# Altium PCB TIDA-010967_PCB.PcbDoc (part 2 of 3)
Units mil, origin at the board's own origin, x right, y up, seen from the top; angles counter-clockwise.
Board outline 2322.7 x 960 mil, 2 copper layers (Top Layer, Bottom Layer), stack 44.731 mil thick; 178 components, 80 nets, 496 pads, 399 vias.
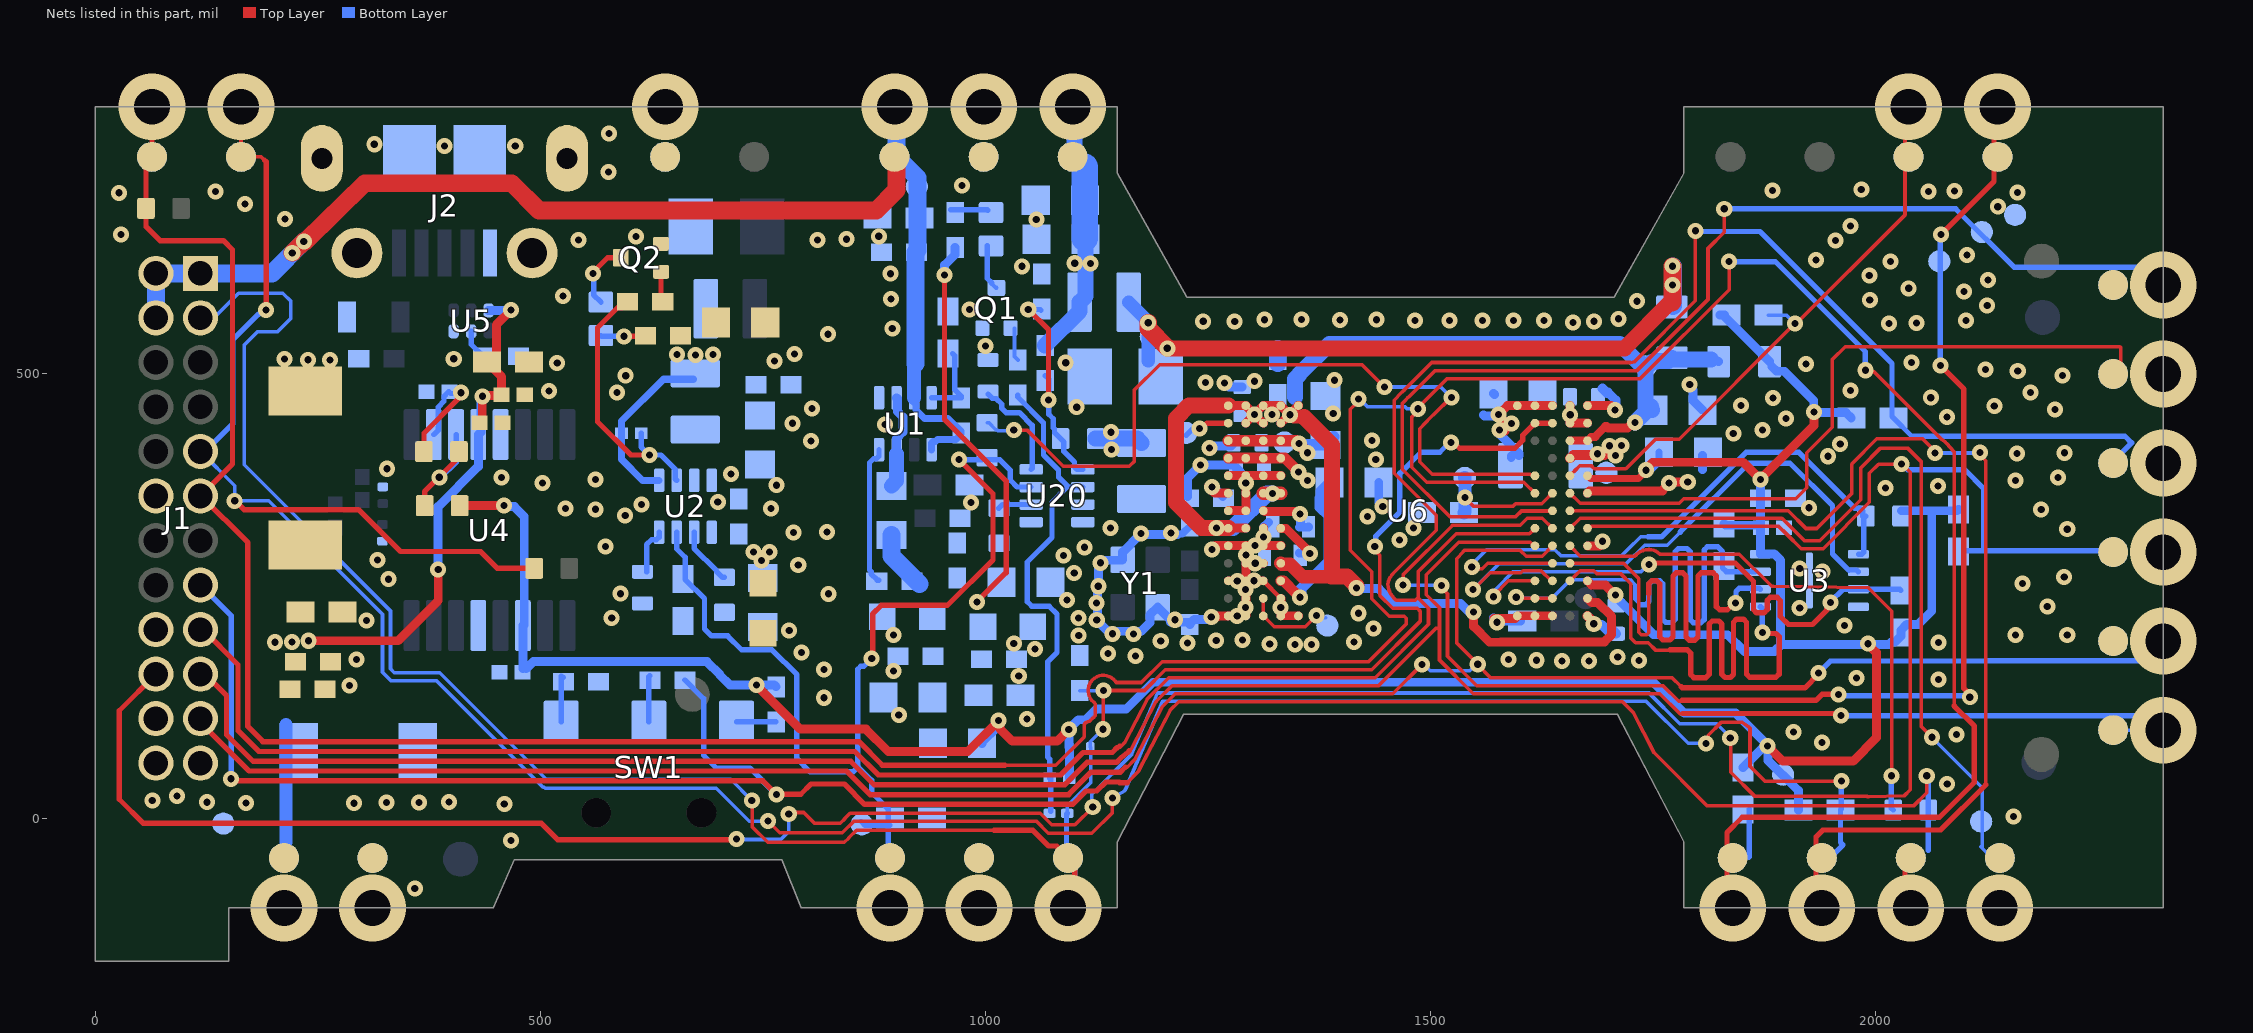
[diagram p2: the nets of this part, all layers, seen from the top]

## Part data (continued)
R14 R15: library part CMP-0027082-3, "RES, 27, 5%, 0.05 W, 0201", Manufacturer="Yageo America", Power_W=50mW, Supplier Part Number 1=YAG2291CT-ND, TempCo="200 ppm/C", Tolerance_%=5%, Value2=0.05W, Value_Code=27R0, ValueDisplayed=27
R19: library part CMP-0026557-2, "RES, 7.87 k, 1%, 0.063 W, AEC-Q200 Grade 0, 0402", Manufacturer=Vishay-Dale, Power_W=63mW, Supplier Part Number 1=541-7.87KLCT-ND, TempCo="100 ppm/C", Tolerance_%=1%, Value2=0.063W, Value_Code=7k87, ValueDisplayed=7.87k
R21: library part CMP-0026574-2, "RES, 82.5 k, 1%, 0.063 W, AEC-Q200 Grade 0, 0402", Manufacturer=Vishay-Dale, Power_W=63mW, Supplier Part Number 1=541-82.5KLCT-ND, TempCo="100 ppm/C", Tolerance_%=1%, Value2=0.063W, Value_Code=82k5, ValueDisplayed=82.5k
R22: library part CMP-0120016-1, "33.2 Ohms ±1% 0.063W, 1/16W Chip Resistor 0402 (1005 Metric) Thin Film", Digikey Part Number=13-RT0402FRE0733R2LCT-ND, Manufacturer=Yageo, Mouser Part Number=603-RT0402FRE0733R2L, Operating Temperature Range="-55°C to +155°C", Power_W=63mW, TempCo=50ppm/°C, Tolerance_%=1%
R23 R175: library part CMP-0027261-3, "RES, 100 k, 1%, 0.05 W, 0201", Manufacturer=Vishay-Dale, Power_W=50mW, Supplier Part Number 1=541-100KAABCT-ND, TempCo="100 ppm/C", Tolerance_%=1%, Value2=0.05W, Value_Code=100k
R26 R244: library part CMP-0026727-1, "RES, 1.00 M, 1%, 0.063 W, 0402", Manufacturer="Yageo America", Power_W=63mW, Supplier Part Number 1=311-1.00MLRCT-ND, TempCo="100 ppm/C", Tolerance_%=1%, Value2=0.063W, Value_Code=1M00, ValueDisplayed=1.00M
R27 R180: library part CMP-0094741-1, "Res Thick Film 0402 18K Ohm 1% 1/16W ±100ppm/°C Molded SMD Paper T/R", Digikey Part Number=541-4757-1-ND, Manufacturer=Vishay, Mouser Part Number=71-CRCW040218K0FKEDC, Operating Temperature Range="-55°C to +155°C", Power_W=63mW, TempCo=100ppm/°C, Tolerance_%=1%
R28 R29 R172 R179: library part CMP-0026704-1, "RES, 510, 1%, 0.1 W, 0402", Manufacturer=Panasonic, Power_W=100mW, Supplier Part Number 1=P510LCT-ND, TempCo="100 ppm/C", Tolerance_%=1%, Value2=0.1W, Value_Code=510R, ValueDisplayed=510
R50: library part CMP-0095013-1, "Res Thick Film 0402 47.5K Ohm 1% 1/16W ±100ppm/°C Molded SMD Paper T/R", Digikey Part Number=13-AC0402FR-0747K5LCT-ND, Manufacturer=Yageo, Mouser Part Number=603-AC0402FR-0747K5L, Operating Temperature Range="-55°C to +155°C", Power_W=62.5mW, TempCo=100ppm/°C, Tolerance_%=1%
R165: library part CMP-0095015-1, "Res Thick Film 0201 10K Ohm 0.5% 0.05W ±50ppm/°C Molded SMD Pressed Carrier T/R", Digikey Part Number=P15980CT-ND, Manufacturer=Panasonic, Mouser Part Number=667-ERJ-1RHD1002C, Operating Temperature Range="-55°C to +125°C", Power_W=50mW, TempCo=50ppm/°C, Tolerance_%=0.5%
R176: library part CMP-0086442-2, "RES SMD 0 OHM JUMPER 1/20W 0201", Manufacturer=Yageo, Power_W=50mW, TempCo=200ppm/°C, Tolerance_%=5%
SW1: library part CMP-0096333-1, "Slide Switch SPDT Surface Mount, Right Angle", Coil Resistance_ohm=80mΩ, Contact Current Rating=100mA, Digikey Part Number=401-2012-1-ND, Manufacturer="C&K Switches", Mouser Part Number=611-AYZ0102AGRLC, Operating Temperature Range="-10°C to +60°C"
TP2 TP4 TP6 TP7 TP8 TP9 TP10 TP11 TP12 TP13 TP14 TP15 TP16 TP17 TP18 TP19: library part CMP-0078143-4, "TEST POINT.  No entry in BOM.", Manufacturer=N/A
U1: library part CMP-0088593-2, "1.6 V to 5 V, 2.5-A Low IQ Power Mux With Manual and Automatic Switchover", Manufacturer="Texas Instruments", Max Supply Voltage=5.5V, Min Supply Voltage=1.6V, Nominal Supply Current=0.5-1uA, Operating Temperature Range=to, Output Voltage=0-5.5V
U2: library part CMP-0092337-2, "2.7-V to 6-V, 2-A Automotive Step-Down Converter in SOT583 Package", Manufacturer="Texas Instruments", Max Supply Voltage=6V, Min Supply Voltage=2.7V, Nominal Supply Current=17uA, Operating Temperature Range="-40°C to +150°C", Output Voltage=0.6-5.5V, Switching Frequency=1.8-4MHz
U3: library part CMP-0078466-1, "ULTRA LOW POWER, 16M-BIT [x 1/x 2/x 4] CMOS MXSMIO (SERIAL MULTI I/O) FLASH MEMORY, SON-8", Manufacturer="Macronix International Co., LTD", Supplier Part Number 1=1092-1178-1-ND
U4: library part CMP-0065473-1, "USB to UART, SSOP-16", Manufacturer=FTDI, Supplier Part Number 1=768-1135-1-ND
U5: library part CMP-0043115-3, "4-Channel ESD Protection Array for High-Speed Data Interfaces, DRY0006A (USON-6)", Breakdown Voltage(Min)(V)=6, IO Capacitance(Typ)(pF)=1.6, IO Leakage Current(nA)=1, Manufacturer="Texas Instruments", Operating Temperature Range="-40 to 85 C", Rating=Catalog
U6: library part CMP-0120794-2, Manufacturer="Texas Instruments", Operating Temperature Range=to
U20: library part CMP-0120069-1, "2.7-V to 6-V, 2-A Step-Down Converter in SOT583 Package", Manufacturer="Texas Instruments", Max Supply Voltage=6V, Min Supply Voltage=2.7V, Nominal Supply Current=17uA, Operating Temperature Range="-40°C to +150°C", Output Voltage=0.6-5.5V, Switching Frequency=1.8-4MHz
Y1: library part CMP-0120019-1, "Crystal Resonator 40MHz ±10ppm (Tol) ±20ppm (Stability) 8pF 50Ohm 4-Pin SMD T/R", Frequency Stability=20ppm, Frequency Tolerance=10ppm, Frequency_Fixed=40MHz, Load Capacitance=8pF, Manufacturer=Murata, Operating Temperature Range="-40°C to +105°C"
ZZ1: library part CMP-0003616-3
ZZ2: library part CMP-0077236-1
ZZ3: library part CMP-0077237-1
ZZ4 ZZ5: library part CMP-0077238-1

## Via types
v1: diameter 18, hole 8, Top Layer to Bottom Layer, tented both sides, 370 vias
v2: diameter 75, hole 40, Top Layer to Bottom Layer, 26 vias
v3: diameter 118.11, hole 118.11, Top Layer to Bottom Layer, tented both sides, 3 vias

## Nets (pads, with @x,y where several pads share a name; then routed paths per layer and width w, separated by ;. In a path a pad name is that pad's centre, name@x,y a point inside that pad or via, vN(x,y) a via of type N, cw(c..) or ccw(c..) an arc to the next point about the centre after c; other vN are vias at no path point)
5V_IN_USB: C25.1 C28.1 C29.2 C30.1 C32.2 C33.1 C36.1 C37.1 C38.1 C45.1 D1.1 J29.1 R5.2 U2.1 U4.12 U5.6 | length 769.7
  Top Layer w10: v1(239.57,200.14) 340.07,200.14 385.22,245.29 v1@385.22,279.99 ; C38.1@431.45,444.93 434.56,448.04 v1@434.56,474.59 ; v1(434.7,474.73) 435.54,475.57 455.58,475.57 C37.1@456.41,476.41 456.41,496.53 C36.1@439.77,513.17 443.71,513.17 450.52,519.98 450.52,555.1 v1(467.07,571.65)
  Bottom Layer w10: v1@384.98,280.22 384.98,350.79 430.24,396.05 U4.12@430.24,431.73 433.18,434.66 433.18,474.29 v1@433.59,474.7 ; U5.6@441.8,571.28 466.7,571.28 v1(467.07,571.65)
  Bottom Layer w15: 214.09,-26.26 214.09,105.87 C33.1@214.09,76.51
  other v1: 201.89,198.46 221.07,198.63 385.13,280.08 748.2,290.16 739.09,300.01 757.16,300.01
  other v2: 212.04,-100
DC_OUT_3V3: C19.1 C49.1 C50.1 L2.2 L3.1 R23.1 R28.1 U2.5 | length 195.3
  Bottom Layer w8: U2.5@633.26,380.3 614.74,380.3 591.06,403.99 591.06,446.91 638.05,493.9 L2.2@671.99,493.9
  other v1: 674.34,521.2 653.5,521.63 693.89,521.63
GND: C1.2 C3.2 C4.2 C5.1 C6.2 C7.2 C8.1 C9.1 C10.2 C11.2 C13.2 C14.1 C15.2 C16.2 C17.1 C18.2 C19.2 C20.1 C21.2 C22.2 C23.2 C25.2 C26.2 C27.1 C28.2 C29.1 C30.2 C31.1 C32.1 C33.2 C34.1 C35.2 C36.2 C37.2 C38.2 C39.2 C40.2 C41.1 C42.1 C43.2 C44.2 C45.2 C46.1 C47.1 C48.1 C49.2 C50.2 C56.2 C60.2 C69.2 C72.2 C73.2 C74.2 C128.2 C129.2 J1.12 J1.18 J1.22 J1.23 J1.24 J2.5 J2.6 J2.7 J2.8 J2.9 J2.10 J2.11 J21.1 J25.1 J28.1 J32.1 Q1.2 Q2.2 R2.1 R10.1 R16.1 R21.1 R25.2 R26.2 R27.2 R180.2 R244.2 TP11.1 TP15.1 U1.1 U2.8 U3.4 U3.9 U4.5 U4.13 U5.3 U6.A1 U6.A3 U6.A4 U6.A5 U6.A6 U6.A7 U6.A9 U6.A10 U6.B7 U6.B9 U6.C8 U6.C9 U6.C10 U6.D8 U6.D9 U6.E1 U6.E7 U6.E8 U6.E9 U6.E10 U6.F8 U6.G9 U6.G10 U6.H1 U6.H9 U6.J7 U6.J8 U6.J9 U6.J10 U6.N1 U6.N3 U6.N4 U6.N5 U20.8 Y1.2 Y1.4 | length 1542.4
  Top Layer w5: U6.C8@1311.9,267.38 U6.B7@1331.58,247.7
  Top Layer w10: v1@1253.42,222.94 1253.42,223.77 1256.59,226.95 1260.08,226.95 1261.12,227.98 U6.A10@1272.39,227.98 ; v1(1254.44,302.6) 1258.76,306.92 U6.E9@1292.21,306.92 ; U6.A10@1272.59,228.18 1292.28,228.18 U6.C9@1292.28,267.55 ; U6.C10@1272.59,267.55 U6.C9@1292.28,267.55 ; U6.G10@1272.59,346.29 1292.28,346.29 1292.28,365.98 1292.22,366.03 v1(1292.22,377.16) ; U6.J10@1272.59,385.66 U6.J9@1292.21,385.66 ; U6.E9@1292.21,306.75 1292.49,307.02 v1(1302.62,307.02) ; U6.E9@1292.21,306.75 U6.D9@1292.28,287.24 ; U6.J9@1292.28,385.66 U6.J7@1331.65,385.66 ; U6.C8@1311.9,267.55 U6.C9@1292.28,267.55 ; U6.D8@1311.96,287.24 U6.D9@1292.28,287.24 ; U6.E8@1311.96,306.92 U6.E7@1331.65,306.92 ; U6.E8@1311.96,307.02 v1(1311.96,316.81) U6.F8@1311.96,326.61 ; U6.B7@1331.65,247.7 1331.65,228.18 U6.A6@1351.33,228.18 ; v1@1571.22,224.97 1594.51,224.97 U6.A5@1595.58,226.03 ; v1@1583.42,435.71 1583.42,446.74 v1(1576.05,454.1) 1586.18,464.23 U6.N5@1597.33,464.23 ; U6.A5@1597.4,228.18 U6.A3@1636.77,228.18 ; U6.N5@1597.4,464.4 U6.N3@1636.77,464.4 ; U6.N1@1676.07,464.23 1702.73,464.23 v1@1707.99,458.97 ; U6.H1@1676.14,365.98 1678.35,368.19 1760.37,368.19 1760.37,369.75 v1(1767.77,377.15) 1768.92,378.31 v1(1788.67,378.31) ; U6.E1@1676.37,306.68 1689.35,306.68 v1@1692.59,309.92 ; U6.C9@1292.28,267.55 U6.D9@1292.28,287.24
  Top Layer w11: U6.A1@1676.07,228.01 1684.35,219.73 v1@1684.35,217.5
  Bottom Layer w8: 1217.08,320.24 1220.83,320.24 C46.1@1229.42,328.84 ; v1(1254.44,302.6) v1@1254.44,304.89
  Bottom Layer w10: v1@1215.37,319.3 1173.99,319.3 1173.76,319.53 1153.95,299.71 Y1.2@1153.95,291.08 1153.39,290.52 1132.53,290.52 1126.67,284.66 1126.67,261.37 1125.69,260.39 1125.69,224.12 v1(1124.83,223.26) 1137.31,210.79 1174.9,210.79 1184.54,220.42 1184.54,229.15 Y1.4@1193.32,237.93 1208.7,222.54 1207.53,221.38 1207.53,220.96 C47.1@1229.56,220.96 ; C6.2@1226.57,362.2 1226.57,382.66 v1(1241.29,397.38) 1278.34,397.38 C9.1@1281.43,394.28 1292.22,383.49 v1(1292.22,377.16) ; C47.1@1229.56,218.22 1229.56,219.26 1234.41,224.1 1251.58,224.1 v1@1252.89,225.41 ; v1@1250.71,417.52 1252.16,418.98 1275.71,418.98 1278.58,421.85 C20.1@1278.58,422.3 ; v1(1268.51,489.86) 1273.43,484.94 C14.1@1288.21,484.94 ; v1(1311.96,316.81) 1311.96,327.52 C22.2@1317.74,333.3 ; C13.2@1328.14,516.13 C13.2@1328.14,516.13 ; 1328.14,532.03 1328.3,532.19 ; C23.2@1441.56,377.89 1441.56,355.42 v1(1446.07,350.91) ; 1559.42,453.79 1560.56,452.65 v1@1575.53,452.65 ; v1@1570.52,225.96 1574.46,222.02 C43.2@1601.03,222.02 ; C26.2@1570.65,477.81 C26.2@1571.65,476.81 ; v1@1574.56,435.02 1599.19,410.39 C27.1@1599.19,408.28 ; C27.1@1590.42,406.19 C27.1@1590.42,407.85 ; 1699.02,479.49 1707.99,470.52 v1@1707.99,458.97 ; v1(1790.89,488.04) 1790.89,485.88 1794.68,482.09 1794.68,469.87 C15.2@1805.42,459.12 ; 1805.01,392.38 1805.19,392.38 C21.2@1805.19,408.39
  Bottom Layer w11: 1692.17,217.84 1699.62,210.38 1705.88,210.38 C17.1@1708.25,208.01 ; C5.1@1692.83,483.52 1697.94,478.41
  Bottom Layer w20: C13.2@1328.06,512.06 1328.06,527.96
  other v1: 358.85,-78.02 466.78,-24.35 2154.77,2.83 459.39,16.83 169.13,18.06 290.6,17.68 125.64,18.79 326.88,18.43 363.52,18.55 397.2,19 63.97,20.57 91.72,25.93 2080.13,39.32 1939.53,86.06 2090.68,94.94 1907.55,97.84 1046.59,112.44 902.46,116.63 818.57,136.12 285.64,149.97 2070.54,156.61 1978.4,158.48 1037.22,160.35 896.6,166.09 818.36,167.83 1618.85,178.25 1647.3,177.54 1677.64,177.44 1733.91,178.07 293.5,179.17 1587.39,178.95 1710.01,181.87 1168.32,183.09 1137.68,185.83 793.1,186.76 1055.55,190.76 1347.39,195.73 1365.88,196.06 1031.67,196.85 1319.14,196.36 1226.59,197.47 2070.4,198.03 1413.91,198.58 1196.72,200.05 1259.04,200.42 1288.53,201.16 1104.59,206 896.73,206.7 2156.91,206.45 2214.94,206.45 1142.37,207.95 1166.11,207.8 779.38,211.79 1435.66,214.06 1964.84,217.41 1683.09,219.18 1574.33,220.86 304.39,222.71 1212.71,223.73 580.01,225.72 1104.28,225.74 1253.47,226.77 1282.6,228.09 1418.88,231.02 1914.45,237.11 1292.14,237.62 1331.48,237.48 2192.51,238.64 1124.76,242.65 1091.44,245.75 590,252.96 823.59,252.88 1292.01,257.91 1126.55,261.37 2164.71,264.48 1282.73,267.07 1301.67,267.56 329.23,269.27 2211.53,271.8 1099.52,276.43 1940.03,277.95 1914.45,281.33 789.56,285.2 1302.85,287.2 1129.05,287.71 316.85,290.78 1087.63,295.96 1292.62,296.65 1110.92,305.14 573.2,305.85 1693.09,311.86 1464.96,313.13 1174.62,320.74 1208.07,321.16 784.26,321.93 821.71,322.19 2214.94,325.44 1140.13,326.59 1480.66,326.69 1428.75,339.53 595.2,340.83 561.65,347.8 2185.68,347.38 528.02,348.74 758.99,348.76 1924.86,349.5 613.44,353.16 983.72,355.31 699.17,356.2 2010.7,371.52 2069.68,374.14 765.02,374.85 502.46,377.34 2156.91,380.06 561.68,381.34 456.05,383.44 2204.7,383.47 713.93,387.29 327.83,393.35 1438.25,403.8 1946.4,407.39 2158.37,410.29 2212.01,411.27 1251.35,416.72 1959.92,421.23 803.67,424.6 1433.88,425.24 1839.81,432.97 1577.32,437.05 1872.83,436.84 887.22,443.12 1590.61,443.99 782.97,444.39 1899.01,449.93 2079.86,451.45 1390.44,455.46 1707.13,459.29 2201.28,460.03 804.99,461.22 1102.36,462.44 1848.44,464.2 2133.01,463.93 1884.43,472.83 2061.66,473.14 586.06,479.02 2173.49,479.05 509.56,480.52 1971.42,481.34 1246.87,490.39 1302.14,491.67 1391.81,492.81 595.76,497.83 2209.57,498.07 2159.35,502.94 2123.26,504.89 1921.41,511.18 518.8,512.24 1090,512.41 2039.95,512.88 762.92,514.26 402.59,516.85 785.29,522.18 999.93,531.35 822.76,544.44 895.18,550.73 2014.87,556.57 2045.59,556.86 1659.96,557.6 1244.41,558.99 1279.82,558.64 1683.57,558.99 1482.21,559.68 1521.1,560.03 1558.24,560.03 1592.96,559.68 1627.33,559.68 2101.12,559.67 1313.15,560.72 1354.81,561.07 1398.2,560.37 1439.17,560.72 1710.99,561.76 981.85,572.09 2125.04,576.59 1731.82,581.55 1993.16,583.07 893.91,583.82 525.15,587.4 2099.12,592.3 2036.85,596.04 2125.77,605.26 1992.58,610.42 893.34,612.43 1041,620.76 2016.43,626.11 1932.84,627.89 2102.25,633.24 810.99,650.1 1954.83,649.87 542.54,650.36 843.66,651.15 607.38,654.1 880.04,654.45 28.82,656.42 1971.46,665.94 213.23,673.95 1056.93,673.46 2136.95,687.66 167.98,690.68 26.45,703.31 2159.14,703.64 134.99,704.9 2059.12,704.84 1883.79,705.69 2088.44,705.4 1983.58,706.81 973.55,711.61 576.26,726.5 392.38,755.74 471.67,756 313.34,757.85 576.79,769.7
  other v2: 311.39,-100 992.59,-100 640.07,800 997.82,800
GPIO_2: J8.1 U6.H2 | length 797.5
  Top Layer w4: U6.H2@1656.45,365.98 1667.74,354.68 1779.23,354.68 1784.1,359.56 1909.89,359.56 1922.43,372.1 1922.43,411.32 1951.16,440.06 1951.16,516.09 1965.64,530.57 2274.14,530.57 2275.15,529.56 2275.15,508.31 J8.1@2266.57,499.73
  other v2: 2322.82,499.73
GPIO_4: R7.1 U6.J4 | length 875.1
  Top Layer w4: v1(1031.65,436.8) 1046.56,436.8 1087.34,396.03 1161.48,396.03 1167.19,401.73 1167.19,482 1195.44,510.25 1422.86,510.25 v1(1447.93,485.18) ; v1(1523.13,473.37) 1522.73,473.37 1503.19,453.82 1502.99,453.82 1491.04,441.88 1491.04,441.68 1487.65,438.29 1487.65,401.17 1501.52,387.3 1611.75,387.3 1612.44,386.61 1615.9,386.61 U6.J4@1617.02,385.49
  Bottom Layer w4: R7.1@1001.68,445.12 1003.85,445.12 1003.85,444.91 1011.49,437.27 1012.75,437.27 1013.83,436.19 1031.04,436.19 v1(1031.65,436.8) ; v1(1447.93,485.18) 1511.31,485.18 v1(1523.13,473.37)
HOST_INTR_GPIO_5: J4.1 R24.2 U6.J2 | length 649.2
  Top Layer w4: U6.J2@1659.69,388.91 1661.58,390.8 ; 1661.54,390.84 1667.31,396.61 1680.39,396.61 1680.59,396.41 1683.77,393.23 1719.27,393.23 1752.49,426.45 1779.01,426.45 1780.29,427.73 1904.49,551.93 1906.23,551.93 2032.7,678.4 v2@2032.7,800
  Bottom Layer w4: R24.2@1879.39,565.99 1899.29,565.99 v1@1907.71,557.57
  other v1: 1908.97,556.46
  other v2: 2036.65,800
NetC2_2: C2.2 R1.1 R2.2 U20.5 | length 252.5
  Top Layer w6: v1(1047.9,572.28) 1070.59,549.59 v1@1070.59,470.57
  Bottom Layer w6: v1(1047.9,572.28) 1061.31,572.28 R2.2@1062.25,571.35 ; C2.2@1066.97,497.78 1070.91,493.84 1070.91,454.64 1076.02,449.52 1076.02,439.45 1077.35,438.13 1077.35,433.97 1087.94,423.38 1087.94,412.82 1099.84,400.92 1099.84,395.42 1102.75,392.51 U20.5@1109.3,392.51
  other v1: 1070.68,470.45
NetC40_1: C40.1 R13.1 U4.10 | length 149.5
  Top Layer w6: R13.1@369.12,412.51 369.12,433.26 405.92,470.05 408.46,472.59 408.46,476.56 v1@409.78,477.88
  Bottom Layer w6: U4.10@380.24,431.73 385.27,436.75 385.27,462.77 391.73,469.23 391.73,474.62 C40.1@397,479.89 ; C40.1@398.77,478.52 399.4,477.88 v1@409.78,477.88 ; v1@409.78,477.79 v1@410.66,477.79
  other v1: 410.75,478.74
NetD1_2: D1.2 L1.2
  other v1: 238.73,515.72 263.58,515.43 212.68,516.46
NetD2_1: D2.1 Q2.3 | length 72.4
  Top Layer w6: v1(559.08,612.56) 559.08,614.06 575.34,630.31 Q2.3@590.14,630.31
  Bottom Layer w6: v1@559.68,610.18 559.68,588.69 D2.1@567.93,580.44
NetD2_2: D2.2 R28.2 | length 50.7
  Top Layer w6: v1(593.73,542.11) 617.05,542.11 R28.2@617.86,542.92
  Bottom Layer w6: D2.2@567.93,543.04 568.87,542.11 v1(593.73,542.11)
NetD3_1: D3.1 Q1.3 | length 52.2
  Bottom Layer w4.8: 1001.86,607 1001.97,607.1 ; Q1.3@1006.65,601.46 1011.61,596.5 Q1.3@1012.23,596.5
  Bottom Layer w6: 1001.86,607 Q1.3@1007.03,601.83 ; 1001.97,607.1 D3.1@1001.97,644.19
NetD3_2: D3.2 R172.2 | length 41.8
  Bottom Layer w6: R172.2@961.03,684.13 1001.99,684.13 D3.2@1002.59,683.53
NetL4_1: L4.1 U1.2 U1.7 | length 102.6
  Bottom Layer w10: U1.7@899.98,414.75 899.98,427.59 907.22,434.84 907.22,451.4 900.88,457.74 900.88,472.11 U1.2@899.98,473.02
  Bottom Layer w17: L4.1@894.26,374.11 899.94,379.8 U1.7@899.94,410.06
NetQ1_1: Q1.1 R179.1 | length 36.6
  Bottom Layer w4.5: Q1.1@1032.53,550.72 1032.53,519.2 R179.1@1036.12,515.61
NetQ2_1: Q2.1 R29.1 | length 33.5
  Top Layer w6: Q2.1@635.42,614.57 635.42,585.39 R29.1@638.48,582.33
NetR3_1: R3.1 U20.2 | length 37.8
  Bottom Layer w6: R3.1@1014.95,349.1 1019,353.14 U20.2@1051.03,353.14
NetR5_1: R5.1 U2.2 | length 65.9
  Bottom Layer w6: U2.2@672.63,322.04 672.63,303.94 697.69,278.89 697.69,278.16 704.53,271.32 R5.1@706.5,271.32
NetR12_2: R12.2 R13.2 U4.11 | length 128.1
  Top Layer w6: R12.2@369.94,351.84 369.94,367.78 406.72,404.56 R13.2@406.72,407.64
  Bottom Layer w6: v1(386.36,383.78) 388.5,383.78 405.24,400.52 U4.11@405.24,431.73
NetR16_2: R16.2 U5.2 | length 33.8
  Bottom Layer w6: U5.2@422.12,547.65 422.12,533.19 R16.2@435.78,519.53
NetR20_2: R20.2 SW1.2 | length 52.2
  Bottom Layer w6: SW1.2@621.72,109.24 621.72,159.85 R20.2@622.86,160.99
NetR22_2: R22.2 U6.E2 | length 620.7
  Top Layer w4: U6.E2@1656.39,306.75 1667.95,295.18 1681.73,295.18 1729.01,295.18 1730.84,297.01 ; 1730.03,295.96 cw(c1744.98,282.56) 1745.13,302.64 cw(c1745,285.64) 1757.22,297.45 1846.44,297.45 1880.22,264.21 1883.03,261.45 1884.63,261.43 1991.44,259.88 1992.59,258.73 2017.89,233.43 v1@2017.89,48.62
  Bottom Layer w6: v1@2017.4,48.13 2017.4,12.04 R22.2@2019.49,9.95
  other v1: 2017.75,48.48
NetR27_1: R27.1 U2.4 | length 53.8
  Bottom Layer w6: R27.1@619.5,277.35 619.32,277.52 619.32,308.1 624.86,313.63 630.36,313.63 633.26,316.54 U2.4@633.26,322.04
NetR180_1: R180.1 U20.4 | length 116.9
  Bottom Layer w6: R180.1@1002.72,477.08 1007.6,472.2 1011.84,472.2 1018.28,465.77 1018.28,461.12 1022.96,456.43 1027.62,456.43 1027.74,456.31 1038.12,456.31 1052.33,442.1 1052.33,393.81 U20.4@1051.03,392.51
NetTP10_1: TP10.1 U6.M10 | length 52.6
  Top Layer w6: v1@1239.31,438.03 1242.31,438.03 1248.83,444.55 U6.M10@1272.53,444.55
  Bottom Layer w6: TP10.1@1225.54,431.1 1232.47,438.03 v1@1239.31,438.03
  other v1: 1240.22,438.53
OUT_3V3: C1.1 C3.1 J1.1 J1.2 J1.4 J22.1 R9.2 TP6.1 U1.3 U1.5 | length 1456
  Top Layer w20: v1@221.31,635.88 v1(234.13,648.47) v1@235.08,648.47 ; v1@235.79,648.46 302.56,714.06 467.7,714.06 498.31,683.45 877.11,683.45 900,706.33 J22.1@900,743.75
  Bottom Layer w8: U1.3@920.35,467.32 921.83,465.84 921.83,459.22 931.23,449.83 957.46,449.83 965.83,441.46 966.61,441.46 972.45,435.61 972.45,432.09 966.61,426.24 945.94,426.24 943.63,423.94 941.25,423.94 939.35,422.03 U1.5@939.35,414.75
  Bottom Layer w10: 919.66,509.66 920.71,510.7
  Bottom Layer w15: 920.71,510.7 921.27,511.27 ; C1.1@922.31,636.34 C1.1@924.64,638.67
  Bottom Layer w16: U1.3@919.66,473.02 919.66,509.66
  Bottom Layer w20: J1.4@68.1,562.73 J1.2@68.1,612.73 198.38,612.73 v1(234.13,648.47) ; v2@900,800 900,743.75 923.6,720.15 923.6,675.03 C1.1@923.6,638.75 ; 921.27,511.27 C1.1@921.27,636.42
  other v1: 221.2,635.77
  other v2: 897.82,800
PMIC_CLKOUT_SOP1: R25.1 TP8.1 U6.H3 | length 146.6
  Top Layer w4: v1@1538.8,360.26 1548.01,351.05 1592.37,351.05 1595.27,353.95 ; 1595.5,353.96 1624.66,353.96 1629.15,358.44 ; 1629.16,358.43 U6.H3@1636.27,365.53
  Bottom Layer w15: R25.1@1537.38,344 1538.45,345.07 v1(1538.45,360.86) 1538.45,382.76 TP8.1@1538.18,383.04
QSPI_CS: R50.2 U3.1 U6.D3 | length 678.6
  Top Layer w4: v1@1545.3,281.26 1557.87,281.26 ; 1557.87,280.97 1563.96,287.07 U6.D3@1636.7,287.07 ; U6.D3@1636.65,287.12 U6.D3@1636.77,287.24
  Bottom Layer w4: v1@1541.51,281.26 1562.68,302.43 1639.44,302.43 1646.02,295.85 1714.55,295.85 1721.33,302.64 1735.73,317.03 1744.09,317.03
  Bottom Layer w6: 1744.22,316.9 1759.17,316.9 1854.05,411.78 1913.51,411.78 1976.45,348.85 1981.95,348.85 1985.13,345.66 R50.2@1985.13,340.16 ; U3.1@1980.4,297.32 1984.28,297.32 1986.2,299.24 1986.2,337.58 R50.2@1988.79,340.16
  other v1: 1546.08,282.92
QSPI_D0: U3.5 U6.C2 | length 675.1
  Top Layer w4: U6.C2@1656.39,267.38 1663.2,274.19 1667.9,278.88 1678.91,278.88 1683.12,278.91 1686.85,275.19 1695.44,275.19 1703.89,275.19 1713.68,275.19 1724.65,264.21 1724.65,203.24 1730.06,197.83 1744.35,197.83 1752.47,189.71 1768.57,189.71
  Top Layer w6: 1768.74,189.88 1788.46,189.88 1791.98,186.37 1791.98,162.23 1795.49,158.72 1809.18,158.72 1812.69,162.23 1812.69,218.8 1816.21,222.31 1823.54,222.31 1827.06,218.8 1827.06,162.44 1830.57,158.92 1836.54,158.92 1840.05,162.44 1840.05,220.95 1843.57,224.47 1851.13,224.47 1854.65,220.95 1854.65,162.64 1858.16,159.13 1887.84,159.13 1891.36,162.64 1891.36,204.82 1887.84,208.34 1873.57,208.34 v1(1872.43,209.48)
  Bottom Layer w6: U3.5@1870.16,238.26 1870.51,238.26 1872.43,236.34 v1(1872.43,209.48)
QSPI_D1: U3.2 U6.C3 | length 675.3
  Top Layer w4: v1@1547.1,256.85 1566.69,276.44 1601.24,276.44 1603.69,278.89 1621.96,278.92 ; 1623.91,278.95 1635.48,267.38 U6.C3@1636.7,267.38
  Bottom Layer w4: v1@1547.76,257.8 1576.82,286.85 1719.67,286.85 1740.23,307.41 1765.49,307.41 1780.16,322.08
  Bottom Layer w6: 1780.16,322.08 1857.6,399.52 1903.62,399.52 1951.31,351.83 1951.31,297.59 U3.2@1969.89,279.01 ; U3.2@1969.89,279.55 1978.26,279.55 U3.2@1980.29,277.52
  other v1: 1547.61,257.8
QSPI_D2: R44.1 U3.3 U6.C4 | length 629.4
  Top Layer w4: v1(1570.39,249.63) v1@1571.65,250.88 ; v1@1571.15,251.38 1587.15,267.38 U6.C4@1617.02,267.38
  Top Layer w6: v1(1745,285.64) 1746.82,287.45 1842.03,287.45 1862.47,267.01 1862.47,234.97 1865.98,231.45 1874.32,231.45 1877.84,234.97 1877.84,245.32 1881.35,248.83 1889.07,248.83 1892.59,245.32 1892.59,227.5 1901.72,218.37 1928.8,218.37 1944.71,234.28 1944.71,235.57 1949.17,240.03 v1(1949.17,243.28)
  Bottom Layer w4: v1(1570.39,249.63) 1573.07,252.31 1573.07,258.16 1592.76,277.85 1736.52,277.85 1744.3,285.64 v1(1745,285.64)
  Bottom Layer w6: v1(1949.17,243.28) 1949.17,244.16 1962.95,257.95 2026.66,257.95 R44.1@2028.01,256.59
QSPI_D3: R49.1 U3.7 U6.B3 U6.B4 | length 668.4
  Top Layer w4: v1@1594.81,248.08 1595.02,247.87 U6.B3@1636.77,247.87
  Bottom Layer w4: v1@1595.02,247.87 1636.14,247.87 1652.49,264.21 1657.13,268.85 1723.72,268.85 1728.36,264.21 1729.2,263.38 ; 1729.39,263.18 1729.39,246.73 1735.43,240.69
  Bottom Layer w6: v1@1594.81,248.08 v1@1595.02,247.87 ; 1735.43,240.69 1741.51,240.69 1745.02,244.2 1745.02,264.12 1748.54,267.64 1757.05,267.64 1760.56,264.12 1760.56,224.11 1764.08,220.6 1771.14,220.6 1774.65,224.11 1774.65,252.98 1774.65,300.32 1778.17,303.84 1787.89,303.84 1791.4,300.32 1791.4,252.98 1791.4,223.88 1794.92,220.36 1803.58,220.36 1807.09,223.88 1807.09,302.07 1810.61,305.58 1822.47,305.58 1827.72,300.33 1827.72,282.09 1832.1,277.7 U3.7@1863.84,277.7
  other v1: 1596,249.05
QSPI_SCLK: U3.6 U6.D2 | length 671.3
  Top Layer w4: U6.D2@1656.39,286.97 1716.72,286.97 1725.81,277.88 ; 1725.83,277.89 1733.69,270.02 1733.69,209.73 1736.4,207.02 ; 1736.4,206.83 1742.42,206.83 1744.76,209.18 1744.76,252.98
  Top Layer w6: 1744.76,252.98 1744.76,264.12 1748.28,267.64 1753.68,267.64 1757.2,264.12 1757.2,252.98 1757.2,204.49 1760.71,200.97 1768.68,200.97 1772.19,204.49 1772.19,272.94 1775.71,276.45 1783.16,276.45 1786.67,272.94 1786.67,204.4 1790.19,200.88 1796.62,200.88 1800.13,204.4 1800.13,272.94 1803.65,276.45 1817.24,276.45 1820.75,272.94 1820.75,252.98 1820.75,238.47 1824.27,234.96 1833.39,234.96 1840.9,242.47 v1(1842.15,242.47)
  Bottom Layer w6: v1(1842.15,242.47) 1842.96,243.27 1842.96,252.98 1842.96,255.43 1846.47,258.95 1869.16,258.95 U3.6@1870.16,257.95
RADAR_1P2_RF: C20.2 C44.1 TP14.1 U6.L7 U6.L8 U6.L9 U6.L10 | length 136.6
  Top Layer w13: U6.L10@1272.59,425.03 v1@1349.01,425.03 ; v1@1352.18,422.84 1352.18,420.73 v1(1361.62,411.29)
  Bottom Layer w13: v1@1351.69,423.41 1355,420.11 C44.1@1381.93,420.11 C44.1@1391.18,429.35
  other v1: 1352.01,421.92
RADAR_1V2: C27.2 TP13.1 U6.K2 | length 61.4
  Top Layer w10: v1@1695.03,410.68 v1@1699.21,414.3 ; v1@1711.76,417.82 v1@1713.36,417.71
  Top Layer w11: U6.K2@1656.39,405.18 1660.14,408.93 v1@1695.03,408.93
  Top Layer w12: v1@1699.21,414.3 1703.92,418.38 v1@1711.76,417.82
  other v1: 1707.5,408.26 1687.42,410.15 1700.69,419.14 1714.1,419.42
RADAR_1V4_APLL: C22.1 U6.G8 | length 68.7
  Top Layer w10: U6.G8@1311.96,346.29 1312.95,346.29 1313.82,345.41 1354.37,345.41 v1@1355.66,344.12
  Bottom Layer w10: 1352.73,327.66 1353.68,327.66 ; v1@1352.9,341.26 1353.68,340.48 1353.68,327.66 ; C22.1@1362.73,328.1 1362.29,327.66 1353.68,327.66
  other v1: 1353.34,342.7
RADAR_1V4_SYNTH: C18.1 U6.F7 | length 57.1
  Top Layer w10: U6.F7@1331.58,326.44 1337.33,326.44 1364.15,299.62 v1(1364.15,298.19)
  Bottom Layer w10: C18.1@1352.66,298.99 1352.75,298.9 v1@1364.57,298.9
RADAR_1V8: C13.1 C14.2 C15.1 R6.2 R11.1 TP12.1 U6.B1 U6.D7 U6.F9 U6.F10 U6.H7 U6.H8 U6.L1 U6.L2 U6.M7 U6.M8 U6.M9 U6.N6 U6.N7 U6.N8 U6.N9 U6.N10 | length 1823.5
  Top Layer w9: U6.L2@1656.39,424.86 U6.L1@1676.07,424.86 1679.96,428.75 1685.07,428.75 ; 1684.45,429.38 1695.97,440.9
  Top Layer w10: U6.F10@1272.59,326.61 U6.F9@1292.28,326.61 ; U6.N10@1272.59,464.4 1292.28,464.4 1292.28,463.87 v1@1301.99,454.42 ; U6.M9@1292.28,444.72 v1@1301.99,454.42 ; U6.M8@1311.96,444.72 1302.16,454.25 v1@1301.99,454.42 ; U6.M7@1331.65,444.72 1331.77,444.72 v1@1337.22,450.16 ; v1@1341.11,454.55 1331.65,464.01 1331.65,464.4 1311.96,464.4 v1@1301.99,454.42 ; v1@1341.3,454.72 1350.98,464.4 U6.N6@1351.33,464.4 ; v1@1343.15,451.76 1345.69,449.23 1357.72,449.23 ; v1@1548.17,232.25 1548.17,216.24 1565.96,198.45 1578.6,198.45 1579.1,198.95 1695.06,198.95 1703.09,206.98 1703.09,227.46 1687.62,242.93 1680.8,242.93 U6.B1@1676.07,247.7 ; 1695.97,440.9 1697.23,440.9 1699.02,439.11 1720.95,439.11 1727.12,445.28 v1(1729.28,445.28)
  Top Layer w15: U6.H8@1311.96,365.98 U6.H7@1331.65,365.98 ; U6.D7@1331.58,287.07 1332.6,286.05 1342.25,286.05 1356.09,272.21 1388.59,272.21
  Top Layer w18: U6.F10@1272.59,326.61 1242.56,326.61 1213.92,355.24 1213.92,449.95 1228.38,464.4 U6.N10@1272.59,464.4 ; 1357.72,451.2 1388.86,420.06 1388.86,272.21 ; 1388.59,272.21 1388.86,272.21 ; v1(1416.58,259.3) 1416.58,261.66 1406.03,272.21 1388.86,272.21
  Bottom Layer w10: v1@1417.24,258.64 1441.71,258.64 1458.42,241.93 1533.46,241.93 v1@1542.91,232.48 ; R11.1@1823.19,514.01 R11.1@1823.52,513.68
  Bottom Layer w18: v1(1259.21,326.98) 1277.77,326.98 1316.2,365.41 v1(1322.11,365.41) ; 1347.51,473.91 1347.51,494.04 1351.98,498.52 1351.98,499.22 1386.3,533.53 1712.3,533.53 1733.92,511.92 1736.38,511.92 1738.54,509.76 TP12.1@1738.54,508.64 ; v1(1729.28,445.28) 1747.46,463.45 C15.1@1747.62,463.45 ; C15.1@1741.4,463.45 TP12.1@1741.4,504.43 ; TP12.1@1743.67,508.42 1748.77,513.51 1751.7,513.51 1752.32,514.14 1767.17,514.14 R6.2@1770.96,517.93 ; C15.1@1747.62,459.12 C15.1@1748.31,459.12 ; R6.2@1770.96,515.84 R11.1@1814.59,515.84
  other v1: 1547.98,232.45 1302.03,454.12 1321.88,454.12 1341.83,453.98
RADAR_1V_RF_OUT: C9.2 C23.1 U6.C7 U6.K7 U6.K8 U6.K9 U6.K10 | length 278.3
  Top Layer w12: U6.K10@1272.59,405.35 U6.K8@1311.96,405.35 ; U6.K8@1311.9,405.18 U6.K7@1331.58,405.18 ; U6.K7@1331.58,405.35 1336.01,405.35 v1@1351.08,390.28 ; U6.C7@1331.87,267.55 1334.59,267.55 1348.48,253.66 1348.59,253.66 1351.59,250.66 v1@1353.22,250.66 ; v1(1351.32,389.53) 1352.25,389.53 v1(1361.77,380.01)
  Bottom Layer w12: v1(1353.2,248.94) 1354.35,250.09 1354.35,258.52 1385.44,289.61 1385.44,340.45 1375.7,350.18 1375.7,360.12 1376.7,361.12 1376.7,368.14 C23.1@1386.45,377.89
RADAR_3V3: C17.2 C21.1 C34.2 C35.1 C39.1 L7.2 R4.1 R11.2 R12.1 R19.2 R24.1 R44.2 R49.2 R50.1 R73.1 R74.1 R75.1 R165.2 R175.1 TP9.1 U3.8 U4.3 U6.C1 U6.J1 | length 3633.9
  Top Layer w8: U6.J1@1676.07,385.49 1676.57,385.49 1679.58,382.48 1733.49,382.48 v1@1739.6,388.59
  Top Layer w10: R12.1@409.31,351.84 R12.1@409.31,351.84 459.07,351.89 v1(459.13,351.94) ; v1(742.46,150.29) 791.94,100.81 865.55,100.81 890.6,75.76 979.93,75.76 v1(1014.57,110.4) 1016.1,108.86 1016.1,101.48 1030.12,87.47 1080.29,87.47 v1(1093.45,100.63) ; U6.C1@1676.07,267.38 1680.76,262.7 1696.14,262.7 v1@1707.41,251.43 ; v1@1741.01,392.46 1749.18,400.62 1850.98,400.62 v1@1870.67,380.93 ; v1@1870.55,382.01 1930.67,442.13 v1(1930.67,457.21) ; v1(1878.25,82.07) 1895.4,64.92 1974.36,64.92 2000.62,91.18 2000.62,186.8 v1@1991.2,196.23
  Bottom Layer w8: v1(1741.76,391.71) 1746.49,391.71 1757.15,402.37 1756.28,403.24 C21.1@1756.28,411.93
  Bottom Layer w10: v1(459.13,351.94) 460.21,350.86 470.63,350.86 481.84,339.65 U4.3@481.84,218.03 ; C39.1@480.24,168.78 U4.3@480.24,217.16 ; C39.1@484.01,168.78 491.96,176.73 687.02,176.73 701.96,161.78 ; 701.67,161.49 712.6,150.56 762.52,150.56 R19.2@764.63,148.44 ; L7.2@995.83,84.96 995.83,85.94 v1@1013.04,103.16 ; R175.1@1094.16,45.81 1094.16,80.16 R165.2@1093.95,80.38 1093.45,80.87 v1(1093.45,100.63) 1104.21,111.39 1112.43,111.39 1124.51,123.46 1158.01,123.46 1188.02,153.48 1750.16,153.48 1784.78,118.87 1842.46,118.87 v1@1878.76,82.58 ; C17.2@1713.06,244.31 1750.43,206.94 1833.3,206.94 1852.1,188.14 1885.92,188.14 1894.79,197 ; R24.1@1825.07,565.99 R24.1@1830.06,565.99 ; R49.2@1829.52,331.59 1831.26,329.84 C34.2@1867.84,329.84 ; R24.1@1831.25,563.03 R11.2@1880.61,513.68 ; R73.1@1850.85,57.9 v1@1875.02,82.07 ; U3.8@1870.16,297.32 U3.8@1870.4,297.56 ; C35.1@1870.4,357.2 U3.8@1870.4,297.56 ; C35.1@1870.43,359.96 v1@1870.43,383.8 ; v1@1878.9,82.07 1878.9,65.48 1879.19,65.48 TP9.1@1896.17,48.49 ; R11.2@1883.07,508.21 1888.4,502.88 1897.25,502.88 1930.24,469.9 v1@1930.24,457.21 ; 1893.03,197 1893.03,290.48 1885.74,297.77 1870.62,297.77 U3.8@1870.4,297.56 ; 1893.61,195.82 2014.49,195.82 2017.26,198.6 2021.2,198.6 2028.01,205.41 2028.01,211.63 2034.82,218.44 2047.69,218.44 2062.8,233.56 2062.8,346.12 ; TP9.1@1896.31,48.63 1913.03,31.91 R74.1@1913.03,10.2 ; v1@1930.24,456.56 1966.31,456.56 R4.1@1972.36,450.51 ; R50.1@2028.62,346.12 2062.8,346.12 ; R75.1@2092.97,347.8 2091.29,346.12 2062.8,346.12
  other v1: 1991.05,196.83 1707.65,251.49 1870.55,381.2
RADAR_NRST: C48.2 J1.3 J3.1 R165.1 R176.1 U6.M3 U6.M4 | length 2673.6
  Top Layer w4: v1@743.57,22.4 737.66,16.49 737.66,-8.64 755.3,-26.28 841.33,-26.28 846.09,-21.52 846.09,-21.27 851.36,-16 851.61,-16 855.02,-12.59 1009.82,-12.59 ; v1(1131.7,100.75) 1132.21,101.26 v1(1132.21,144.28) 1178.49,144.28 1201.96,167.74 1433.9,167.74 1488.01,221.85 1488.01,233.53 1484.94,236.59 1457.24,236.59 1443.07,250.76 ; v1(1437.17,305.95) 1437.17,302.16 1441.65,297.68 1441.65,297.21 1442.89,295.97 1442.89,251.95
  Top Layer w6: 1009.82,-12.83 1053.22,-12.83 1070.75,-30.37 1079.74,-30.37 J3.1@1099.04,-49.67 ; v2@1100,-100 J3.1@1100,-43.75 ; v1(1522.66,422.94) 1525.65,422.94 1532.23,416.36 1594.5,416.36 1603.29,425.16 1603.29,430.82 U6.M4@1617.02,444.55 U6.M3@1636.7,444.55 1636.85,444.55 U6.M3@1637.24,444.15
  Bottom Layer w4: J1.3@118.1,562.73 133.15,562.73 160.89,590.47 210.57,590.47 219.71,581.32 219.71,562.21 204.52,547.02 181.98,547.02 167.28,532.31 ; 167.37,532.31 167.37,397.72 331.53,233.55 331.53,168.61 335.82,164.33 386.92,164.33 506.65,44.59 672.58,44.59 ; 672.58,44.48 713.62,44.48 v1(737.37,20.73) ; R176.1@1091.77,6.3 1091.77,14.74 1117.98,40.95 R165.1@1117.98,80.38 ; C48.2@1105.76,144.09 1131.04,144.09 v1@1132.38,145.43 ; R165.1@1117.57,80.38 1117.57,86.7 v1@1131.62,100.75
  Bottom Layer w6: R176.1@1091.77,6.3 1090.91,5.44 1090.91,-39.14 J3.1@1093.24,-41.47 ; v2@1100,-100 J3.1@1100,-43.75 ; v1@1438.04,305.95 1438.04,317.42 1465.31,344.7 1465.31,388.23 1488.98,411.9 1510.13,411.9 v1@1523.15,424.91
  other v2: 1092.59,-100
RADAR_OSC_CLKOUT: TP7.1 U6.A8 U6.B8 | length 102.2
  Top Layer w4: U6.B8@1311.96,247.87 1311.96,228.18 1324.25,215.9 1359.06,215.9 v1@1371.52,228.36
  Bottom Layer w4: v1@1371.57,231.69 1377.05,226.21 TP7.1@1381.98,226.21
  other v1: 1371.52,228.46
RADAR_SRAM_1V2: C5.2 C26.1 U6.M1 U6.M2 U6.N2 | length 39.4
  Top Layer w10: U6.N2@1656.45,464.4 1656.45,444.72 U6.M1@1676.14,444.72
  other v1: 1656.64,453.93
RADAR_VBGAP: C6.1 U6.H10 | length 42.9
  Top Layer w10: v1@1250.22,373.16 1257.4,365.98 U6.H10@1272.59,365.98
  Bottom Layer w10: v1@1253.96,374.75 C6.1@1266.34,362.37
  other v1: 1254.47,372.88
REG_1V8: C11.1 L6.2 R6.1 TP2.1 | length 788.6
  Top Layer w18: v1(1204.07,528.67) 1717.64,528.67 1769.64,580.67 1771.69,580.67
  Top Layer w20: v1(1182.67,557.4) 1182.67,550.77 v1@1204.07,529.37 ; 1770.86,579.84 1771.69,580.67 v1(1771.69,620.86)
  Bottom Layer w15: L6.2@1160.66,580.52 1182.85,558.33 C11.1@1182.85,514.41 ; R6.1@1770.96,575.02 R6.1@1772.17,576.22
  Bottom Layer w20: R6.1@1772.17,576.22 v1@1772.17,620.39
  other v1: 1771.4,599.84
REG_3V3: C4.1 C10.1 C56.1 C60.1 C69.1 C72.1 C73.1 C74.1 L4.2 L7.1 R3.2 R8.1 R172.1 U20.1 | length 513.8
  Top Layer w6: v1(953.83,611.07) 953.83,448.81 1023.01,379.63 1023.01,276.62 v1@989.96,243.57
  Bottom Layer w10: v1(953.83,611.07) 953.83,622.14 965.67,633.98 R172.1@965.67,641.96
  Bottom Layer w20: L4.2@894.26,318.99 894.26,295.45 R8.1@925.79,263.91
  other v1: 990.53,243.57
REG_MODE_SELECT: J26.1 R7.2 R26.1 R244.1 TP4.1 U2.3 U20.3 | length 1143.8
  Top Layer w6: v1(872.05,180.3) 873.14,181.39 873.14,230.21 882.96,240.03 957.29,240.03 1008.33,291.07 1008.33,365.28 v1@970.03,403.59
  Bottom Layer w6: U2.3@652.95,322.04 652.95,303.46 662.5,293.91 662.5,269.06 684.18,247.38 684.18,213.58 692.08,205.67 710.28,205.67 726.09,189.86 760.11,189.86 787.91,162.06 787.91,67.68 802.73,52.86 851.27,52.86 856.91,58.5 ; TP4.1@860.31,-2.84 864.62,-7.14 R244.1@892.27,-7.14 ; v1(872.05,180.3) 863.28,171.53 859.8,171.53 856.28,168.02 856.28,59.12 871.93,43.48 871.93,29.96 890.56,11.33 J26.1@890.56,-37.54 ; J26.1@895.05,-37.54 895.05,-38.8 J26.1@900,-43.75 ; v1@966.99,401.69 968.88,403.59 R7.2@1003.84,403.59 ; R7.2@1004.11,403.31 1015.99,403.31 1027.79,391.52 1027.79,380.41 1035.37,372.83 U20.3@1051.03,372.83
  other v1: 970.03,403.9
  other v2: 892.59,-100
REG_OUT_1V8: C2.1 C128.1 C129.1 J24.1 L6.1 L15.2 R1.2 | length 345.8
  Bottom Layer w18: C2.1@1066.97,531.81 1105.54,570.38 L6.1@1105.54,580.52 1112.37,587.36 C129.1@1112.37,651.17 C129.1@1111.44,652.11 ; v2@1100,800 1100,743.75 1111.44,732.31 ; R1.2@1123.56,427.13 1170.35,427.13 L15.2@1175.21,422.27
  Bottom Layer w30: C129.1@1111.44,652.11 C128.1@1111.44,695.03 1111.44,732.31
  other v1: 1141.27,415.16 1140.91,434.41 1100.13,624.16 1118.02,623.86
  other v2: 1097.82,800
REG_PG_1V8: R175.2 R176.2 R179.2 U20.6 | length 558.1
  Bottom Layer w6: R179.2@1036.12,476.24 1036.12,473.87 1065.02,444.97 1065.02,409.02 1081.96,392.08 1081.96,383.86 1092.99,372.83 ; R175.2@1072.19,45.89 1072.19,66.92 1069.62,69.49 1069.62,176.51 1080.26,187.14 1080.26,230.02 1071.36,238.91 1051.98,238.91 1046.8,244.09 1046.8,288.42 1074.51,316.13 1074.51,355.74 1091.59,372.83 1092.99,372.83 ; R176.2@1073.21,8.53 R175.2@1073.21,45.81 ; U20.6@1109.3,372.83 1092.99,372.83
REG_PG_3V3: R23.2 R29.2 U2.6 | length 301.4
  Top Layer w6: R29.2@597.97,581.19 591.13,574.35 586.81,574.35 564.14,551.68 564.14,446.14 601.51,408.78 v1(622.31,408.78)
  Bottom Layer w6: R23.2@613.1,433.23 613.1,417.98 v1(622.31,408.78) 635.21,408.78 U2.6@651.53,392.46 ; U2.6@651.26,391.56 651.26,382 U2.6@652.95,380.3
RS232_RX: J1.9 J7.1 J27.1 R17.1 R74.2 U6.G2 | length 4390.4
  Top Layer w4: v2(163.65,800) J27.1@163.65,743.75 186.14,743.75 189.99,739.9 ; v1(755.38,-2.17) 768.64,-15.43 839.15,-15.43 851.74,-2.83 1057.36,-2.83 1070.52,-16 1119.36,-16 1142.48,7.13 v1(1142.48,23.57) ; U6.G2@1656.39,346.12 1656.47,346.04 1901.63,346.04 1921.42,326.25 1933.51,326.25 1972.8,365.55 1972.8,398.64 2001.12,426.95 2052.34,426.95 v1@2065.86,413.43 ; v1(1809.21,84.87) 1811.89,87.54 1811.89,94.16 1826.11,108.38 1850.08,108.38 1857.19,103.38 1858.61,101.96 1858.61,59.1 1875.42,42.28 1960.75,42.28 v1(1961.24,42.78) ; v1(2116.94,411.64) 2116.94,408.72 2123.36,402.3 2123.36,38.33
  Top Layer w6: v1@156.57,357.05 157.55,357.05 167.2,347.4 295.65,347.4 342.72,300.33 432.75,300.33 451.6,281.48 R17.1@492.91,281.48 ; 189.99,739.9 191.86,738.03 v1(191.86,571.83) ; v2@1932.7,-100 1932.7,-43.75 1932.7,-20.14 1940.5,-12.35 2072.68,-12.35 2123.36,38.33
  Bottom Layer w4: J1.9@118.1,412.73 156.57,374.26 v1(156.57,357.38) 194.98,357.38 322.53,229.82 322.53,164.89 332.1,155.33 383.19,155.33 502.92,35.59 504.31,35.59 505.37,34.53 697.48,34.53 734.69,-2.68 754.87,-2.68 v1(755.38,-2.17) ; v1(1142.48,23.57) 1156.08,31.57 1157,32.48 1198.94,132.4 1741.54,132.4 1789.08,84.87 1808.74,84.87 v1@1808.93,84.67 ; v1(2066.35,411) 2115.69,411 v1@2116.29,410.41
  Bottom Layer w6: J1.9@118.1,412.73 123.25,412.73 154.28,443.76 154.28,538.01 183.25,566.98 183.76,566.98 188.61,571.83 v1(191.86,571.83) ; J7.1@1932.7,-43.75 1948.36,-43.75 1963.01,-29.1 1960.27,-26.36 R74.2@1960.27,10.2 1961.24,11.17 v1(1961.24,42.78)
  other v2: 1939.17,-100
RS232_TX: J1.11 J5.1 J31.1 R18.1 R73.2 U6.H4 | length 4463
  Top Layer w4: 1021.63,60.32 1078.91,60.32 1110.69,92.09 1110.69,104.79 1110.69,105.19 1110.77,105.58 cw(c1114.69,104.79) 1113.25,108.52 cw(c1277.2,-319.31) 1116.41,109.72 ccw(c1114.98,113.45) 1118.15,111.01 cw(c1131.7,100.75) 1121.82,114.58 1122.04,114.81 1123.21,115.98 1123.21,129.44 1122.04,130.61 1121.87,130.79 cw(c1132.21,144.28) 1145.7,154.62 1145.88,154.45 1147.05,153.28 1174.76,153.28 1198.23,176.74 1430.17,176.74 1472.31,218.88 1472.31,225.25 1469.97,227.59 1453.51,227.59 1433.89,247.22 1433.89,277.61 1409.56,301.93 1409.56,460.15 1419.01,469.6 v1(1419.01,471.52) ; v1@1485.19,460.16 1485.19,458.01 1478.65,451.47 1478.65,395.15 1495.5,378.3 1604.52,378.3 U6.H4@1617.02,365.81 ; v1(1485.69,460.69) 1485.69,461.71 1518.65,494.67 1735.41,494.67 1835.14,594.4 v1(1835.14,626) ; v1(1988.22,503.98) 1990.07,502.13 1997.95,502.13 2073.81,426.28 cw(c2066.35,411) 2079.21,422.13 2087.87,412.22 2087.89,410.54 2087.89,127.03
  Top Layer w6: v2(63.65,800) J31.1@63.65,743.75 56.91,737.01 R18.1@56.91,685.75 56.91,665.35 72.69,649.56 143.94,649.56 154.13,639.37 154.13,398.75 J1.11@118.1,362.73 118.83,362.73 171.26,310.29 171.26,103.76 188.25,86.78 857.57,86.78 884.03,60.32 1021.63,60.32 ; v2@1832.7,-100 1832.7,-15.33 1849.9,1.87 2071.35,1.87 2110.67,41.2 2110.67,104.25 2087.89,127.03
  Bottom Layer w4: v1(1419.01,471.52) 1420.52,471.52 1428.86,463.18 1470.93,463.18 1473.32,460.79 v1@1485.59,460.79 ; J5.1@1832.7,-43.75 1853.7,-43.75 J5.1@1855.63,-41.82
  Bottom Layer w6: v1(1835.14,626) 1886.96,626 1988.22,524.74 1988.22,504.77 v1@1988.62,504.37 ; 1857.03,-43.22 1857.62,-42.63 R73.2@1857.62,10.7
  other v2: 1839.17,-100
SOP0_H: R19.1 SW1.1 | length 44.6
  Bottom Layer w6: SW1.1@720.14,109.24 720.31,109.07 R19.1@764.63,109.07
SOP0_L: R21.2 SW1.3 | length 51.6
  Bottom Layer w6: SW1.3@523.29,109.24 R21.2@523.29,160.26 ; R21.2@525.39,159.3 R21.2@525.82,158.87
SPI_CLK_I2C_SCL: J1.20 J13.1 R75.2 U6.F1 | length 3524.9
  Top Layer w4: v1(778.9,5.57) 780.57,7.24 795.66,7.24 807.84,-4.95 836.73,-4.95 841.62,-0.05 ; 841.5,0.07 847.74,6.32 1061.45,6.32 1074.43,-6.67 1100.38,-6.67 v1(1120.35,13.31) ; U6.F1@1676.07,326.44 1677.65,326.44 1680.1,328.89 1890.61,328.89 1899.52,319.97 ; v1@1836.32,88.23 1836.95,87.6 1836.95,52.56 1864.22,25.29 1989.26,25.29 1990.27,25.2 ccw(c1991.75,42.14) 1991.49,25.14 1992.02,25.14 2031.64,25.81 2038.48,32.64 2038.48,389.28 v1(2028.96,398.8) 2028.64,398.48 2003.03,398.48 1992.69,388.14 1992.69,355.63 1940.69,303.63 1916.03,303.63 1899.61,320.05
  Top Layer w6: J1.20@68.1,162.73 26.88,121.5 26.88,22.07 53.93,-4.98 501.01,-4.98 519.31,-23.28 719.35,-23.28 v1(720.16,-22.47)
  Bottom Layer w4: v1(720.16,-22.47) 720.77,-23.08 769.9,-23.08 778.9,-14.08 v1(778.9,5.57) ; v1@1119.28,12.92 1119.28,27.63 1163.95,72.3 1193,141.48 1745.19,141.48 1779.81,106.87 1821.25,106.87 1836.32,91.8 v1@1836.32,88.23
  Bottom Layer w6: v1(2028.96,398.8) 2035.57,392.19 2099.98,392.19 2120.8,371.37 2120.8,301.31 ; R75.2@2099.05,302.5 2100.24,301.31 2120.8,301.31 ; J13.1@2266.57,299.73 2264.99,301.31 2120.8,301.31
  other v1: 1836.43,90.85
  other v2: 2322.82,299.73
SPI_CS_I2C_SDA: J1.17 J15.1 R4.2 U6.F4 | length 3197.9
  Top Layer w4: 1150.61,81.48 1150.61,80.58 1150.8,80.4 ; 1150.83,80.4 1151.72,81.06 1155.88,85.22 1181.81,134.87 1205.68,158.74 1437.63,158.74 1497.5,218.61 1497.5,236.76 1486.06,248.2 ; 1484.89,247.94 1482.55,245.59 1462.64,245.59 1461.02,245.59 1458.68,247.94 1455.32,252.43 cw(c1468.93,262.61) 1456.35,274.05 1459.61,277.64 1506.22,324.24 1506.22,341.17 1460.04,387.35 1458.87,388.52 1458.87,459.35 1459.03,460.47 1459.03,470.44 1466.88,478.64 cw(c1485.69,460.69) 1470.01,481.43 1501.25,512.67 1724.27,512.67 1728.92,513.63 1797.17,581.88 1797.17,660.44 v1(1797.38,660.65) ; 1486.06,248.42 1486.06,248.2 ; U6.F4@1617.08,326.61 1610.87,320.4 1572.65,320.4 1528.56,320.4 1486.06,277.9 1486.06,248.2
  Top Layer w6: J1.17@118.1,212.73 120.71,212.73 160.26,173.18 160.26,99.16 183.65,75.78 853.02,75.78 879.48,49.32 1084.23,49.32 1109.48,74.57 1142.29,74.57 1147.78,80.06 1150.59,81.46
  Bottom Layer w6: v1(1797.38,660.65) 1798.16,659.87 1869.69,659.87 2018.04,511.52 2018.04,452.07 R4.2@2019.6,450.51 2040.29,429.82 2279.83,429.82 2287.25,422.39 2266.57,401.71 J15.1@2266.57,399.73
  other v2: 2322.82,399.73
SPI_MISO_REG_MODE: J1.19 J17.1 U6.E4 | length 2706.7
  Top Layer w4: 1161.43,76.44 1161.66,76.21 1163.21,77.76 1191.39,131.72 1191.82,132.15 1209.41,149.74 1441.36,149.74 1505.85,214.23 1509.09,214.23 ; 1509.85,213.86 1509.85,178.52 1547.63,140.74 1757.23,140.74 1779.59,118.38 1782.81,118.38 ; 1509.85,214.23 1509.85,237.14 1495.06,251.93 1495.06,274.18 1531.49,310.6 1611.75,310.6 1615.43,306.92 U6.E4@1617.08,306.92
  Top Layer w6: J1.19@118.1,162.73 123.36,162.73 147.39,138.7 147.39,94.55 177.16,64.78 848.46,64.78 874.92,38.32 1088.79,38.32 1114.04,63.57 1146.85,63.57 1152.33,69.05 1159.8,74.6 1161.43,76.44 ; 1782.81,118.38 1958.53,118.38 v1(1960.83,116.09) ; v2@2291.16,98.82 v2@2304.6,98.82
  Bottom Layer w4: J17.1@2266.57,99.73 v2(2322.82,99.73)
  Bottom Layer w6: v1(1960.83,116.09) 2306.46,116.09 v2(2322.82,99.73)
SPI_MOSI: J1.21 J19.1 U6.E3 | length 2611.3
  Top Layer w4: 1156.88,58.05 1158.93,58.05 1167.23,66.35 1167.95,67.33 1198.8,126.4 1213.14,140.74 1457.45,140.74 v1(1490.25,173.59) ; v1@1551.46,172.77 1551.46,175.42 1529.33,197.55 1529.33,280.02 cw(c1546.08,282.92) 1529.33,285.82 1529.33,292.42 1536.46,300.35 1536.53,300.43 1537.7,301.6 1572.65,301.6 1600.64,301.6 1607.1,295.14 1614.52,295.14 1621.9,295.13 ; v1(1552.78,173.76) 1552.78,173.08 1567.12,158.74 1771.04,158.74 1781.39,148.39 ; 1621.9,295.12 1625.07,295.12 U6.E3@1636.7,306.75 ; U6.E3@1636.7,306.92 U6.E3@1636.77,306.92
  Top Layer w6: J1.21@118.1,112.73 118.1,108.28 172.61,53.78 843.9,53.78 870.37,27.32 1093.35,27.32 1118.6,52.57 1151.4,52.57 1156.88,58.05 ; 1781.39,148.39 1782.55,147.23 1920.31,147.23 v1@1935.64,162.56
  Bottom Layer w4: v1(1490.25,173.59) 1492.19,173.59 1499.35,166.42 1543.85,166.42 1551.86,174.43 v1@1552.42,174.43
  Bottom Layer w6: v1@1937.66,166.26 1948.88,177.49 2122.51,177.49 ; 2135.78,177.49 2122.51,177.49 ; v2(2322.82,199.73) 2300.64,177.54 2122.57,177.54 2122.51,177.49
  other v1: 1935.49,163.83
SW3_1V8: L15.1 U20.7
SW3_3V3: L2.1 U2.7
SW_PR1: R9.1 R10.2 U1.4 | length 87
  Bottom Layer w6: U1.4@939.35,473.02 969.94,473.02 R9.1@972.45,473.02 972.45,474.98 965.26,482.18 965.26,520.43 R10.2@962.82,522.88
SW_ST: R8.2 U1.8 | length 158.6
  Bottom Layer w6: U1.8@880.29,414.75 880.29,407.46 877.39,404.56 874.01,404.56 869.52,400.08 869.52,279.58 871.5,277.6 871.5,275.1 878.35,268.26 R8.2@880.32,268.26
TCK: J10.1 TP17.1 U6.F3 | length 1653.3
  Top Layer w4: v1@1467.88,262.67 1469.3,264.09 1469.3,274.6 1523.98,329.28 ; v1@1511.93,262.21 1511.93,259.78 1518.85,252.87 1518.85,182.6 1551.7,149.74 1760.95,149.74 1778.39,132.31 1781.7,132.31 1782.52,133.12 ; 1524.01,329.83 1600.36,329.83 1608.32,337.8 ; 1608.33,337.78 1625.36,337.78 ; 1625.31,337.9 1625.31,337.83 1625.36,337.78 ; U6.F3@1636.7,326.44 1625.36,337.78
  Top Layer w6: 1782.52,133.12 1932.76,133.12 1939.56,139.92 v1(1957.98,139.92) ; v1(2072.37,509.17) 2098.85,482.7 2098.85,146.62 2106.21,139.27 v1@2106.21,136.51 ; v1(2073.22,656.43) 2132.7,715.91 2132.7,743.75 v2@2132.7,800
  Bottom Layer w4: v1@1462.45,262.59 1463.74,263.89 1469.63,263.89 1470.92,262.59 v1@1505.74,262.59
  Bottom Layer w6: v1(1957.98,139.92) 1959.69,138.22 2104.5,138.22 v1@2106.21,136.51 ; v1(2072.37,509.17) 2072.37,654.45 v1@2074.35,656.43
  other v1: 2105.48,136.75 1512.29,262.21 1468.93,262.61
  other v2: 2136.65,800
TDI: J14.1 TP18.1 U6.F2 | length 962.3
  Top Layer w4: U6.F2@1656.39,326.44 1667.84,337.89 1894.5,337.89 1919.76,312.63 1936.96,312.63 1982.83,358.49 1982.83,394.18 2005.26,416.61 2035.48,416.61 2051.19,400.9 2051.19,103.36 2062.56,91.99 v1@2062.56,91.89
  Bottom Layer w4: v1(2063.14,91.75) 2063.14,91.3 2119.56,34.88 2119.56,-32.89 ; 2117.85,-31.19 2119.56,-32.89 ; J14.1@2132.7,-43.75 2130.42,-43.75 2119.56,-32.89
  other v2: 2139.17,-100
TDO_SOP0: J1.15 J12.1 R20.1 R22.1 | length 2631.1
  Top Layer w4: 1159,40.81 1171.48,53.3 1207.61,122.48 1216.87,131.74 1715.31,131.74 1726.71,120.34 1727.14,119.91 1751.01,74.17 1751.45,73.74 1810.57,14.62 2042.22,14.62 2057.13,29.52 v1(2057.13,48.48)
  Top Layer w6: v1(152.56,45.07) 154.85,42.78 749.72,42.78 v1(765.2,27.3) ; v1@764.49,27.73 792.35,27.73 803.83,39.21 841.28,39.21 864.17,16.32 1097.9,16.32 1112.89,31.31 1124.77,31.31 1135.03,41.57 1149.94,41.57 1150.69,40.81 1159,40.81 ; v2@2032.7,-100 J12.1@2032.7,-43.75
  Bottom Layer w6: J1.15@118.1,262.73 152.56,228.27 v1(152.56,45.07) ; R20.1@662.23,155.99 683.38,134.84 683.38,71.31 697.47,57.22 735.14,57.22 v1@764.69,27.67 ; v1@2058.88,43.77 2058.88,-5.31 2058.93,-35.38
  other v2: 2039.17,-100
TMS: J6.1 TP19.1 U6.G3 | length 1298.2
  Top Layer w4: 1475.89,474.58 1504.98,503.67 1731.69,503.67 1811.4,583.38 1811.4,640.79 1829.76,659.15 v1@1829.76,685.99 ; 1475.89,474.58 ccw(c1485.69,460.69) 1471.81,470.5 1468.03,466.72 1468.03,392.83 1521.54,339.32 1572.65,339.32 1595.29,339.32 1601.88,345.9 ; 1601.92,345.95 1601.88,345.9 ; U6.G3@1636.77,345.9 1601.88,345.9
  Bottom Layer w6: v1(1829.67,685.36) 2089.64,685.36 2155.26,619.74 2302.82,619.74 v2(2322.82,599.73)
